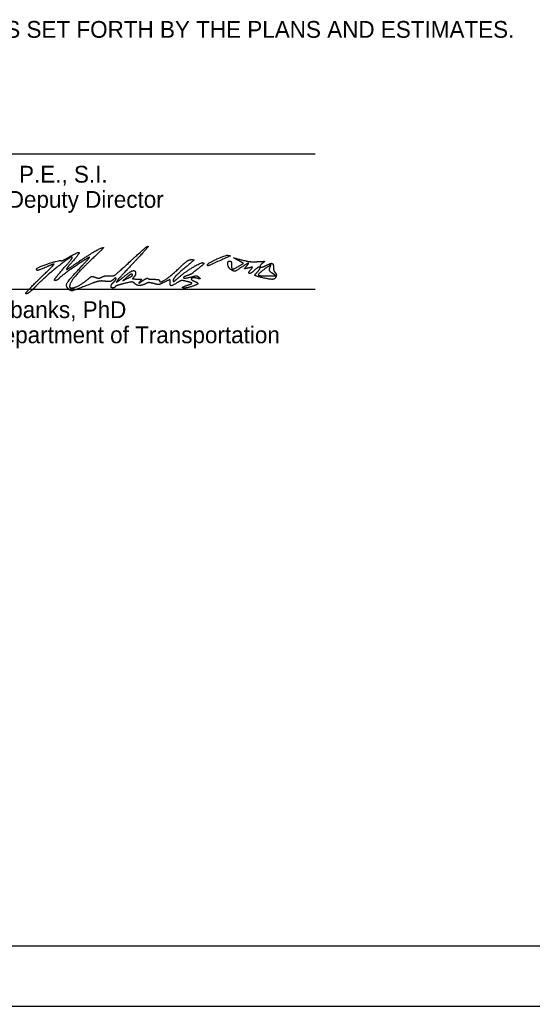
# Model space of a CAD drawing. Extents: x -10 to 89.7, y -4.8 to 22.
# Drawn here: x 25.69 to 29.97, y 0 to 8.23 of the extents above; entities that cross this region are included whole.
import ezdxf

# ---------------------------------------------------------------- set-up
doc = ezdxf.new("R2010")
doc.units = 0
for name, color, linetype in [('GM_X_Minor_Lake', 7, 'Continuous'), ('GM_X_Minor_River', 7, 'Continuous'), ('GM_X_Minor_River_Text', 7, 'Continuous'), ('SH_Text', 7, 'Continuous')]:
    doc.layers.add(name, color=color, linetype=linetype)

msp = doc.modelspace()

# ---------------------------------------------------------------- linework, layer by layer
at = {"layer": 'GM_X_Minor_Lake'}
for p, q in [((24.6564, 7.1081), (28.1564, 7.1081)), ((24.6564, 5.9786), (28.1564, 5.9786))]:
    msp.add_line(p, q, dxfattribs=at)
at = {"layer": 'GM_X_Minor_River'}
msp.add_lwpolyline([(1.5, 21.5), (33.5, 21.5), (33.5, 0.5), (1.5, 0.5)], close=True, dxfattribs=at)
at = {"layer": 'GM_X_Minor_River_Text'}
for p, q in [((27.258, 6.1828), (27.258, 6.1828)), ((26.633, 6.0958), (26.633, 6.0958)), ((25.8559, 6.0648), (25.8559, 6.0648)), ((27.7105, 6.0766), (27.7105, 6.0766))]:
    msp.add_line(p, q, dxfattribs=at)
for points in [[(27.5218, 6.1733), (27.5582, 6.1948), (27.5175, 6.2177)], [(27.7705, 6.0897), (27.8268, 6.0898), (27.798, 6.1119)], [(26.5813, 6.0761), (26.5518, 6.0505), (26.5924, 6.0702)]]:
    msp.add_lwpolyline(points, dxfattribs=at)
for points in [[(26.6154, 6.2133), (26.6904, 6.2824), (26.7564, 6.339), (26.7622, 6.3391)], [(26.7622, 6.3391), (26.7679, 6.3392), (26.7159, 6.279), (26.6465, 6.2054)], [(26.1022, 6.2464), (26.1809, 6.2926), (26.1932, 6.2793), (26.1339, 6.212)], [(26.1611, 6.1929), (26.2417, 6.2495), (26.373, 6.3268), (26.3887, 6.3268)], [(26.3887, 6.3268), (26.3936, 6.3268), (26.3523, 6.2841), (26.2969, 6.2321)], [(27.258, 6.1828), (27.258, 6.1952), (27.4108, 6.2655), (27.4298, 6.2619)], [(27.4298, 6.2619), (27.4504, 6.2578), (27.4512, 6.2582), (27.3295, 6.2036)], [(25.8332, 6.1486), (25.8334, 6.1592), (26.0208, 6.2224), (26.0365, 6.2172)], [(26.1303, 6.2462), (26.1206, 6.2558), (25.9109, 6.0889), (25.833, 6.0096)], [(25.8559, 6.0648), (25.9269, 6.1333), (25.9822, 6.1893), (25.9788, 6.1893)], [(25.9788, 6.1893), (25.9754, 6.1893), (25.9463, 6.178), (25.9143, 6.1643)], [(26.2705, 6.2457), (26.2215, 6.2179), (26.0331, 6.0857), (26.0199, 6.0698)], [(26.0365, 6.2172), (26.0421, 6.2154), (26.0716, 6.2285), (26.1022, 6.2464)], [(26.0524, 6.1458), (26.0987, 6.1975), (26.1337, 6.2427), (26.1303, 6.2462)], [(26.1339, 6.212), (26.1059, 6.1802), (26.083, 6.1505), (26.083, 6.1461)], [(26.083, 6.1461), (26.083, 6.1416), (26.1182, 6.1627), (26.1611, 6.1929)], [(26.2969, 6.2321), (26.1973, 6.1383), (26.108, 6.0302), (26.108, 6.0032)], [(26.2053, 6.1668), (26.2515, 6.216), (26.2808, 6.2516), (26.2705, 6.2457)], [(26.4404, 6.0909), (26.4739, 6.0881), (26.4974, 6.1045), (26.6154, 6.2133)], [(26.6465, 6.2054), (26.517, 6.0679), (26.4849, 6.0206), (26.5671, 6.0884)], [(27.0955, 6.1793), (27.0215, 6.1184), (26.9705, 6.0649), (26.9705, 6.0481)], [(27.0049, 6.0659), (27.0585, 6.1147), (27.2054, 6.2047), (27.2223, 6.1991)], [(27.0236, 6.1571), (27.0688, 6.2009), (27.106, 6.2266), (27.1236, 6.2262)], [(27.1236, 6.2262), (27.1479, 6.2257), (27.1441, 6.2194), (27.0955, 6.1793)], [(27.2223, 6.1991), (27.2307, 6.1963), (27.2155, 6.1776), (27.1884, 6.1573)], [(27.3295, 6.2036), (27.267, 6.1755), (27.258, 6.1729), (27.258, 6.1828)], [(27.459, 6.1387), (27.4325, 6.1529), (27.4216, 6.2143), (27.4455, 6.2143)], [(27.4455, 6.2143), (27.4524, 6.2143), (27.458, 6.2002), (27.458, 6.183)], [(27.458, 6.183), (27.458, 6.1462), (27.4723, 6.144), (27.5218, 6.1733)], [(27.5175, 6.2177), (27.4746, 6.2418), (27.4737, 6.2419), (27.5768, 6.2155)], [(27.5814, 6.1684), (27.6058, 6.198), (27.59, 6.1943), (27.5338, 6.157)], [(27.5768, 6.2155), (27.5974, 6.2102), (27.6424, 6.2074), (27.6768, 6.2094)], [(27.6768, 6.2094), (27.7316, 6.2124), (27.7365, 6.2108), (27.7166, 6.196)], [(27.7166, 6.196), (27.6878, 6.1745), (27.7108, 6.1582), (27.7444, 6.1762)], [(27.7783, 6.1575), (27.7882, 6.1832), (27.78, 6.1802), (27.7174, 6.1346)], [(27.7444, 6.1762), (27.7847, 6.1977), (27.808, 6.192), (27.808, 6.1605)], [(25.9143, 6.1643), (25.8517, 6.1374), (25.8329, 6.1338), (25.8332, 6.1486)], [(25.9866, 6.0518), (25.9763, 6.0518), (26.0052, 6.093), (26.0524, 6.1458)], [(26.0982, 5.9812), (26.073, 6.0064), (26.1019, 6.0565), (26.2053, 6.1668)], [(26.3774, 6.0805), (26.3908, 6.088), (26.4192, 6.0927), (26.4404, 6.0909)], [(26.5671, 6.0884), (26.6155, 6.1283), (26.658, 6.1386), (26.658, 6.1105)], [(26.633, 6.0958), (26.633, 6.1093), (26.6089, 6.1001), (26.5813, 6.0761)], [(26.5924, 6.0702), (26.6147, 6.081), (26.633, 6.0926), (26.633, 6.0958)], [(26.658, 6.1105), (26.658, 6.1016), (26.6513, 6.0875), (26.643, 6.0793)], [(26.858, 6.0503), (26.858, 6.0274), (26.9533, 6.0889), (27.0236, 6.1571)], [(27.0986, 6.0964), (27.0491, 6.0809), (27.0686, 6.0672), (27.1204, 6.0811)], [(27.133, 6.1129), (27.1296, 6.1086), (27.1141, 6.1012), (27.0986, 6.0964)], [(27.1204, 6.0811), (27.1588, 6.0913), (27.174, 6.0907), (27.1861, 6.0784)], [(27.1884, 6.1573), (27.1614, 6.1372), (27.1364, 6.1172), (27.133, 6.1129)], [(27.5338, 6.157), (27.4937, 6.1305), (27.4804, 6.1273), (27.459, 6.1387)], [(27.6008, 6.1567), (27.5677, 6.1485), (27.5659, 6.1496), (27.5814, 6.1684)], [(27.6209, 6.146), (27.6355, 6.1636), (27.6332, 6.1648), (27.6008, 6.1567)], [(27.6496, 6.1372), (27.6177, 6.1073), (27.5946, 6.1143), (27.6209, 6.146)], [(27.6748, 6.1246), (27.7053, 6.1583), (27.6836, 6.1692), (27.6496, 6.1372)], [(27.7105, 6.0766), (27.6558, 6.0896), (27.65, 6.0972), (27.6748, 6.1246)], [(27.7174, 6.1346), (27.6747, 6.1035), (27.6911, 6.0896), (27.7705, 6.0897)], [(27.798, 6.1119), (27.7776, 6.1276), (27.7719, 6.1409), (27.7783, 6.1575)], [(27.808, 6.1605), (27.808, 6.1447), (27.8144, 6.1254), (27.8222, 6.1176)], [(27.8222, 6.1176), (27.83, 6.1098), (27.8329, 6.0946), (27.8288, 6.0839)], [(25.7455, 5.94), (25.7352, 5.9402), (25.7849, 5.9963), (25.8559, 6.0648)], [(25.833, 6.0096), (25.7952, 5.9711), (25.7558, 5.9398), (25.7455, 5.94)], [(26.0199, 6.0698), (26.0117, 6.0599), (25.9967, 6.0518), (25.9866, 6.0518)], [(26.2979, 6.0287), (26.1518, 5.971), (26.1168, 5.9626), (26.0982, 5.9812)], [(26.126, 5.9893), (26.1478, 5.9893), (26.2291, 6.0345), (26.2655, 6.0668)], [(26.2655, 6.0668), (26.2858, 6.0848), (26.2987, 6.0874), (26.3224, 6.0784)], [(26.4034, 6.0458), (26.3742, 6.0495), (26.3344, 6.0431), (26.2979, 6.0287)], [(26.3224, 6.0784), (26.3426, 6.0707), (26.3614, 6.0714), (26.3774, 6.0805)], [(26.4729, 6.0602), (26.4573, 6.046), (26.436, 6.0416), (26.4034, 6.0458)], [(26.4698, 5.9893), (26.4514, 5.9893), (26.456, 6.022), (26.4768, 6.0393)], [(26.4955, 6.0677), (26.4955, 6.0748), (26.4853, 6.0714), (26.4729, 6.0602)], [(26.4768, 6.0393), (26.4871, 6.0478), (26.4955, 6.0606), (26.4955, 6.0677)], [(26.5641, 6.0267), (26.5257, 6.0175), (26.4915, 6.0053), (26.4879, 5.9996)], [(26.6484, 6.0289), (26.6373, 6.04), (26.6172, 6.0395), (26.5641, 6.0267)], [(26.643, 6.0793), (26.6313, 6.0676), (26.6372, 6.0643), (26.6695, 6.0643)], [(26.7447, 6.0263), (26.714, 6.0099), (26.6661, 6.0111), (26.6484, 6.0289)], [(26.6695, 6.0643), (26.7071, 6.0643), (26.7094, 6.0622), (26.6939, 6.0429)], [(26.6939, 6.0429), (26.6819, 6.0279), (26.6884, 6.0296), (26.7157, 6.0488)], [(26.7157, 6.0488), (26.7371, 6.0638), (26.7578, 6.0728), (26.7617, 6.0689)], [(26.8092, 6.0264), (26.7823, 6.0341), (26.7592, 6.0341), (26.7447, 6.0263)], [(26.7617, 6.0689), (26.7656, 6.065), (26.7889, 6.0618), (26.8134, 6.0618)], [(26.8983, 6.0378), (26.8609, 6.0193), (26.8424, 6.0169), (26.8092, 6.0264)], [(26.8134, 6.0618), (26.8379, 6.0618), (26.858, 6.0566), (26.858, 6.0503)], [(26.9455, 6.0377), (26.9455, 6.0606), (26.9444, 6.0606), (26.8983, 6.0378)], [(27.0074, 6.0347), (26.9624, 6.0081), (26.9455, 6.0089), (26.9455, 6.0377)], [(26.9705, 6.0481), (26.9705, 6.0407), (26.986, 6.0487), (27.0049, 6.0659)], [(27.0906, 6.0427), (27.0518, 6.0526), (27.035, 6.051), (27.0074, 6.0347)], [(27.1266, 6.0017), (27.08, 5.9863), (27.0327, 5.9921), (27.0768, 6.0078)], [(27.0768, 6.0078), (27.0905, 6.0127), (27.1102, 6.0197), (27.1205, 6.0235)], [(27.1205, 6.0235), (27.1319, 6.0276), (27.1202, 6.0352), (27.0906, 6.0427)], [(27.1674, 6.071), (27.1306, 6.0801), (27.1174, 6.057), (27.1518, 6.0438)], [(27.1518, 6.0438), (27.1823, 6.0321), (27.1734, 6.0172), (27.1266, 6.0017)], [(27.1861, 6.0784), (27.1988, 6.0655), (27.1952, 6.0641), (27.1674, 6.071)], [(27.8288, 6.0839), (27.8207, 6.0628), (27.7795, 6.0602), (27.7105, 6.0766)], [(26.108, 6.0032), (26.108, 5.9955), (26.1161, 5.9893), (26.126, 5.9893)], [(26.4879, 5.9996), (26.4844, 5.9939), (26.4762, 5.9893), (26.4698, 5.9893)]]:
    msp.add_open_spline(points, degree=2, dxfattribs=at)
at = {"layer": 'SH_Text'}
msp.add_lwpolyline([(0, 0), (34, 0), (34, 22), (0, 22)], close=True, dxfattribs=at)

# ---------------------------------------------------------------- texts
at = {"layer": 'GM_X_Minor_River_Text'}
for s, p in [('WILL BE AS SET FORTH BY THE PLANS AND ESTIMATES.', (24.6564, 8.0758)), ('John Picuri, P.E., S.I.', (24.6564, 6.8681)), ('District       Deputy Director', (24.6564, 6.6581)), ('Jack Marchbanks, PhD', (24.6564, 5.7386)), ('Director, Department of Transportation', (24.6564, 5.5286))]:
    msp.add_text(s, height=0.14, dxfattribs=at).set_placement(p)

doc.saveas('drawing.dxf')
